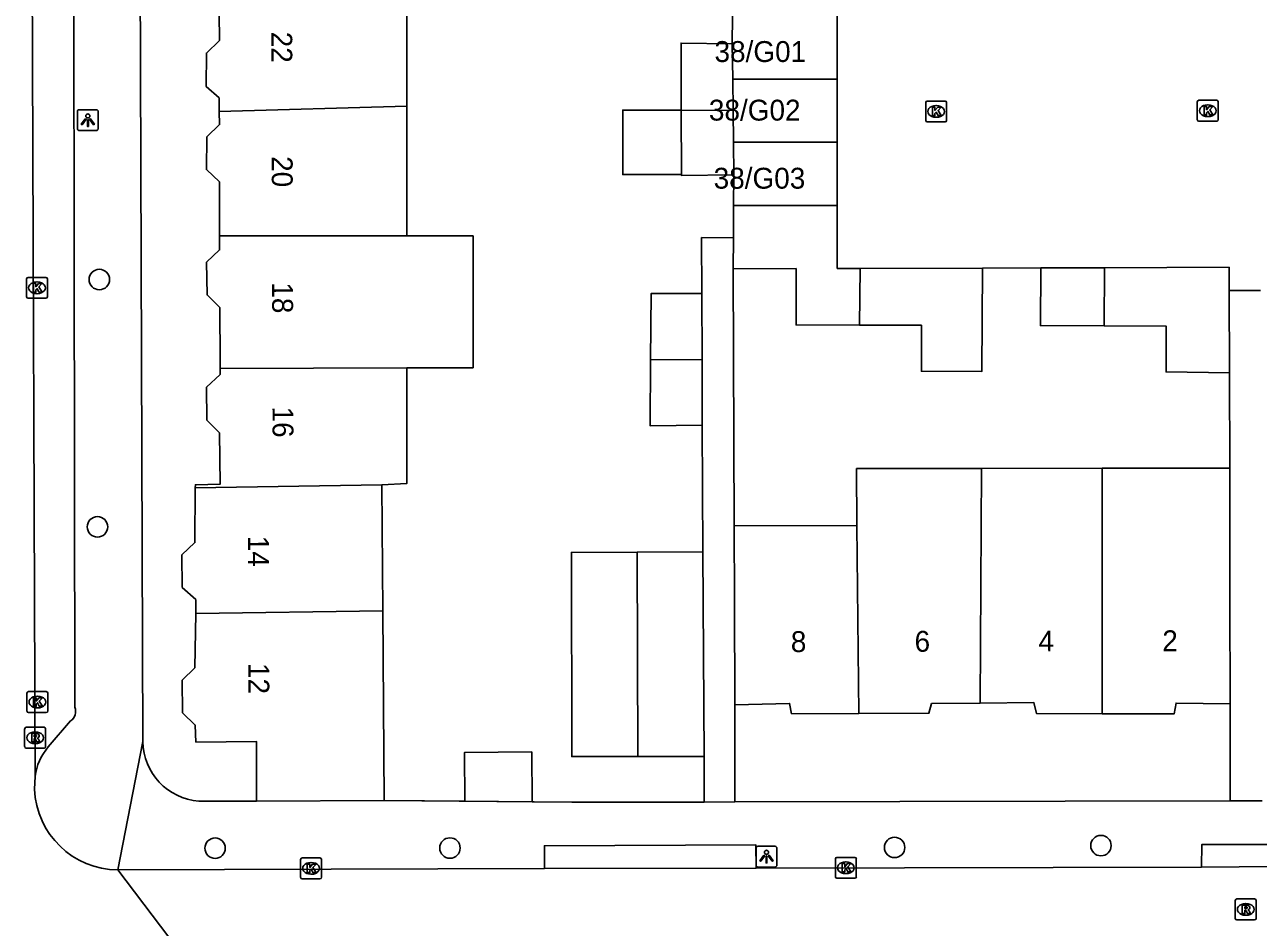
# Model space of a CAD drawing. Extents: x 160732 to 162105, y 387428 to 388479.
# Drawn here: x 161066.2 to 161125.2, y 388054.8 to 388098 of the extents above; entities that cross this region are included whole.
import ezdxf

# ---------------------------------------------------------------- set-up
doc = ezdxf.new("R2010")
doc.units = 0
for name, color, linetype in [('IMGEO_Boom', 7, 'Continuous'), ('IMGEO_Erf', 7, 'Continuous'), ('IMGEO_Kolk', 7, 'Continuous'), ('IMGEO_Lichtpunt', 7, 'Continuous'), ('IMGEO_Muur', 7, 'Continuous'), ('IMGEO_Pand', 7, 'Continuous'), ('IMGEO_Pand_nummerreeks', 7, 'Continuous'), ('IMGEO_Rijbaan_lokaal_open', 7, 'Continuous'), ('IMGEO_Rioolput', 7, 'Continuous'), ('IMGEO_Voetpad_open', 7, 'Continuous')]:
    doc.layers.add(name, color=color, linetype=linetype)

msp = doc.modelspace()

# ---------------------------------------------------------------- linework, layer by layer
at = {"layer": 'IMGEO_Boom'}
for centre in [(161069.729, 388085.825), (161069.639, 388073.982), (161075.27, 388058.596), (161086.512, 388058.605), (161107.794, 388058.632), (161117.671, 388058.72)]:
    msp.add_circle(centre, 0.489, dxfattribs=at)
at = {"layer": 'IMGEO_Erf'}
msp.add_lwpolyline([(161114.79, 388086.385), (161112.001, 388086.377)], dxfattribs=at)
at = {"layer": 'IMGEO_Kolk'}
for p, q in [((161109.283, 388093.446), (161109.283, 388094.298)), ((161109.358, 388094.372), (161110.21, 388094.372)), ((161110.284, 388094.298), (161110.284, 388093.446)), ((161122.283, 388093.482), (161122.283, 388094.334)), ((161122.358, 388094.408), (161123.21, 388094.408)), ((161123.284, 388094.334), (161123.284, 388093.482)), ((161109.771, 388094.152), (161109.796, 388094.152)), ((161122.771, 388094.188), (161122.796, 388094.188)), ((161110.21, 388093.372), (161109.358, 388093.372)), ((161109.794, 388093.592), (161109.769, 388093.592)), ((161123.21, 388093.408), (161122.358, 388093.408)), ((161122.794, 388093.628), (161122.769, 388093.628)), ((161066.245, 388085.002), (161066.245, 388085.854)), ((161066.32, 388085.928), (161067.172, 388085.928)), ((161066.733, 388085.708), (161066.758, 388085.708)), ((161067.246, 388085.854), (161067.246, 388085.002)), ((161067.172, 388084.928), (161066.32, 388084.928)), ((161066.756, 388085.148), (161066.731, 388085.148)), ((161066.263, 388065.167), (161066.263, 388066.019)), ((161066.338, 388066.093), (161067.19, 388066.093)), ((161067.264, 388066.019), (161067.264, 388065.167)), ((161066.774, 388065.313), (161066.749, 388065.313)), ((161066.751, 388065.873), (161066.776, 388065.873)), ((161067.19, 388065.093), (161066.338, 388065.093)), ((161079.362, 388057.205), (161079.362, 388058.057)), ((161079.437, 388058.131), (161080.289, 388058.131)), ((161079.85, 388057.911), (161079.875, 388057.911)), ((161080.363, 388058.057), (161080.363, 388057.205)), ((161104.961, 388057.232), (161104.961, 388058.084)), ((161105.036, 388058.158), (161105.888, 388058.158)), ((161105.449, 388057.938), (161105.474, 388057.938)), ((161105.962, 388058.084), (161105.962, 388057.232)), ((161080.289, 388057.131), (161079.437, 388057.131)), ((161079.873, 388057.351), (161079.848, 388057.351)), ((161105.888, 388057.158), (161105.036, 388057.158)), ((161105.472, 388057.378), (161105.447, 388057.378))]:
    msp.add_line(p, q, dxfattribs=at)
for points in [[(161109.283, 388093.446), (161109.283, 388094.298)], [(161109.358, 388094.372), (161110.21, 388094.372)], [(161110.284, 388094.298), (161110.284, 388093.446)], [(161122.283, 388093.482), (161122.283, 388094.334)], [(161122.358, 388094.408), (161123.21, 388094.408)], [(161123.284, 388094.334), (161123.284, 388093.482)], [(161109.604, 388094.072), (161109.727, 388094.072), (161109.727, 388093.921), (161109.857, 388094.072), (161110.021, 388094.072), (161109.875, 388093.921), (161110.028, 388093.672), (161109.876, 388093.672), (161109.791, 388093.836), (161109.727, 388093.769), (161109.727, 388093.672), (161109.604, 388093.672), (161109.604, 388094.072)], [(161122.604, 388094.108), (161122.727, 388094.108), (161122.727, 388093.957), (161122.857, 388094.108), (161123.021, 388094.108), (161122.875, 388093.957), (161123.028, 388093.708), (161122.876, 388093.708), (161122.791, 388093.872), (161122.727, 388093.805), (161122.727, 388093.708), (161122.604, 388093.708), (161122.604, 388094.108)], [(161110.21, 388093.372), (161109.358, 388093.372)], [(161123.21, 388093.408), (161122.358, 388093.408)], [(161066.245, 388085.002), (161066.245, 388085.854)], [(161066.32, 388085.928), (161067.172, 388085.928)], [(161066.566, 388085.628), (161066.689, 388085.628), (161066.689, 388085.477), (161066.819, 388085.628), (161066.983, 388085.628), (161066.837, 388085.477), (161066.99, 388085.228), (161066.838, 388085.228), (161066.753, 388085.392), (161066.689, 388085.325), (161066.689, 388085.228), (161066.566, 388085.228), (161066.566, 388085.628)], [(161067.246, 388085.854), (161067.246, 388085.002)], [(161067.172, 388084.928), (161066.32, 388084.928)], [(161066.263, 388065.167), (161066.263, 388066.019)], [(161066.338, 388066.093), (161067.19, 388066.093)], [(161067.264, 388066.019), (161067.264, 388065.167)], [(161066.584, 388065.793), (161066.707, 388065.793), (161066.707, 388065.642), (161066.837, 388065.793), (161067.001, 388065.793), (161066.855, 388065.642), (161067.008, 388065.393), (161066.856, 388065.393), (161066.771, 388065.557), (161066.707, 388065.49), (161066.707, 388065.393), (161066.584, 388065.393), (161066.584, 388065.793)], [(161067.19, 388065.093), (161066.338, 388065.093)], [(161079.362, 388057.205), (161079.362, 388058.057)], [(161079.437, 388058.131), (161080.289, 388058.131)], [(161079.683, 388057.831), (161079.806, 388057.831), (161079.806, 388057.68), (161079.936, 388057.831), (161080.1, 388057.831), (161079.954, 388057.68), (161080.107, 388057.431), (161079.955, 388057.431), (161079.87, 388057.595), (161079.806, 388057.528), (161079.806, 388057.431), (161079.683, 388057.431), (161079.683, 388057.831)], [(161080.363, 388058.057), (161080.363, 388057.205)], [(161104.961, 388057.232), (161104.961, 388058.084)], [(161105.036, 388058.158), (161105.888, 388058.158)], [(161105.282, 388057.858), (161105.405, 388057.858), (161105.405, 388057.707), (161105.535, 388057.858), (161105.699, 388057.858), (161105.553, 388057.707), (161105.706, 388057.458), (161105.554, 388057.458), (161105.469, 388057.622), (161105.405, 388057.555), (161105.405, 388057.458), (161105.282, 388057.458), (161105.282, 388057.858)], [(161105.962, 388058.084), (161105.962, 388057.232)], [(161080.289, 388057.131), (161079.437, 388057.131)], [(161105.888, 388057.158), (161105.036, 388057.158)]]:
    msp.add_lwpolyline(points, dxfattribs=at)
for centre, start, end in [((161109.36, 388094.296), 91.55205, 178.44795), ((161109.36, 388094.296), 91.55205, 178.44795), ((161110.208, 388094.296), 1.55205, 88.44795), ((161110.208, 388094.296), 1.55205, 88.44795), ((161122.36, 388094.332), 91.55205, 178.44795), ((161122.36, 388094.332), 91.55205, 178.44795), ((161123.208, 388094.332), 1.55205, 88.44795), ((161123.208, 388094.332), 1.55205, 88.44795), ((161109.36, 388093.448), 181.55205, 268.44795), ((161109.36, 388093.448), 181.55205, 268.44795), ((161110.208, 388093.448), 271.55205, 358.44795), ((161110.208, 388093.448), 271.55205, 358.44795), ((161122.36, 388093.484), 181.55205, 268.44795), ((161122.36, 388093.484), 181.55205, 268.44795), ((161123.208, 388093.484), 271.55205, 358.44795), ((161123.208, 388093.484), 271.55205, 358.44795), ((161066.322, 388085.852), 91.55205, 178.44795), ((161066.322, 388085.852), 91.55205, 178.44795), ((161067.17, 388085.852), 1.55205, 88.44795), ((161067.17, 388085.852), 1.55205, 88.44795), ((161066.322, 388085.004), 181.55205, 268.44795), ((161066.322, 388085.004), 181.55205, 268.44795), ((161067.17, 388085.004), 271.55205, 358.44795), ((161067.17, 388085.004), 271.55205, 358.44795), ((161066.34, 388066.017), 91.55205, 178.44795), ((161066.34, 388066.017), 91.55205, 178.44795), ((161067.188, 388066.017), 1.55205, 88.44795), ((161067.188, 388066.017), 1.55205, 88.44795), ((161066.34, 388065.169), 181.55205, 268.44795), ((161066.34, 388065.169), 181.55205, 268.44795), ((161067.188, 388065.169), 271.55205, 358.44795), ((161067.188, 388065.169), 271.55205, 358.44795), ((161079.439, 388058.055), 91.55205, 178.44795), ((161079.439, 388058.055), 91.55205, 178.44795), ((161080.287, 388058.055), 1.55205, 88.44795), ((161080.287, 388058.055), 1.55205, 88.44795), ((161105.038, 388058.082), 91.55205, 178.44795), ((161105.038, 388058.082), 91.55205, 178.44795), ((161105.886, 388058.082), 1.55205, 88.44795), ((161105.886, 388058.082), 1.55205, 88.44795), ((161079.439, 388057.207), 181.55205, 268.44795), ((161079.439, 388057.207), 181.55205, 268.44795), ((161080.287, 388057.207), 271.55205, 358.44795), ((161080.287, 388057.207), 271.55205, 358.44795), ((161105.038, 388057.234), 181.55205, 268.44795), ((161105.038, 388057.234), 181.55205, 268.44795), ((161105.886, 388057.234), 271.55205, 358.44795), ((161105.886, 388057.234), 271.55205, 358.44795)]:
    msp.add_arc(centre, 0.0765, start, end, dxfattribs=at)
for centre, major_axis, ratio, start_param, end_param in [((161109.77, 388093.872), (-0.387, 0.002), 0.722429, 4.712389, 7.853982), ((161109.795, 388093.872), (-0.39, 0.002), 0.717154, 1.570796, 4.712389), ((161122.77, 388093.908), (-0.387, 0.002), 0.722429, 4.712389, 7.853982), ((161122.795, 388093.908), (-0.39, 0.002), 0.717154, 1.570796, 4.712389), ((161066.732, 388085.428), (-0.387, 0.002), 0.722429, 4.712389, 7.853982), ((161066.757, 388085.428), (-0.39, 0.002), 0.717154, 1.570796, 4.712389), ((161066.75, 388065.593), (-0.387, 0.002), 0.722429, 4.712389, 7.853982), ((161066.775, 388065.593), (-0.39, 0.002), 0.717154, 1.570796, 4.712389), ((161079.849, 388057.631), (-0.387, 0.002), 0.722429, 4.712389, 7.853982), ((161079.874, 388057.631), (-0.39, 0.002), 0.717154, 1.570796, 4.712389), ((161105.448, 388057.658), (-0.387, 0.002), 0.722429, 4.712389, 7.853982), ((161105.473, 388057.658), (-0.39, 0.002), 0.717154, 1.570796, 4.712389)]:
    msp.add_ellipse(centre, major_axis=major_axis, ratio=ratio, start_param=start_param, end_param=end_param, dxfattribs=at)
at = {"layer": 'IMGEO_Lichtpunt'}
for p, q in [((161068.68, 388093.861), (161068.68, 388093.054)), ((161068.68, 388093.861), (161068.68, 388093.054)), ((161069.582, 388093.956), (161068.774, 388093.956)), ((161069.582, 388093.956), (161068.774, 388093.956)), ((161069.676, 388093.054), (161069.676, 388093.861)), ((161069.676, 388093.054), (161069.676, 388093.861)), ((161068.774, 388092.96), (161069.582, 388092.96)), ((161068.774, 388092.96), (161069.582, 388092.96)), ((161101.163, 388058.597), (161101.163, 388057.79)), ((161101.163, 388058.597), (161101.163, 388057.79)), ((161102.065, 388058.692), (161101.257, 388058.692)), ((161102.065, 388058.692), (161101.257, 388058.692)), ((161102.159, 388057.79), (161102.159, 388058.597)), ((161102.159, 388057.79), (161102.159, 388058.597)), ((161101.257, 388057.696), (161102.065, 388057.696)), ((161101.257, 388057.696), (161102.065, 388057.696))]:
    msp.add_line(p, q, dxfattribs=at)
for points in [[(161069.054, 388093.525), (161069.093, 388093.497), (161068.905, 388093.235), (161068.867, 388093.262), (161069.054, 388093.525)], [(161069.156, 388093.477), (161069.203, 388093.477), (161069.203, 388093.155), (161069.156, 388093.155), (161069.156, 388093.477)], [(161069.266, 388093.497), (161069.304, 388093.524), (161069.491, 388093.262), (161069.452, 388093.234), (161069.266, 388093.497)], [(161101.537, 388058.261), (161101.576, 388058.233), (161101.388, 388057.971), (161101.35, 388057.998), (161101.537, 388058.261)], [(161101.749, 388058.233), (161101.787, 388058.26), (161101.974, 388057.998), (161101.935, 388057.97), (161101.749, 388058.233)], [(161101.639, 388058.213), (161101.686, 388058.213), (161101.686, 388057.891), (161101.639, 388057.891), (161101.639, 388058.213)]]:
    msp.add_lwpolyline(points, dxfattribs=at)
for centre in [(161069.179, 388093.659), (161101.662, 388058.395)]:
    msp.add_circle(centre, 0.0994, dxfattribs=at)
for centre, start, end in [((161068.774, 388093.861), 90, 180), ((161068.774, 388093.861), 90, 180), ((161069.582, 388093.861), 0, 90), ((161069.582, 388093.861), 0, 90), ((161068.774, 388093.054), 180, 270), ((161068.774, 388093.054), 180, 270), ((161069.582, 388093.054), 270, 0), ((161069.582, 388093.054), 270, 360), ((161101.257, 388058.597), 90, 180), ((161101.257, 388058.597), 90, 180), ((161102.065, 388058.597), 0, 90), ((161102.065, 388058.597), 0, 90), ((161101.257, 388057.79), 180, 270), ((161101.257, 388057.79), 180, 270), ((161102.065, 388057.79), 270, 0), ((161102.065, 388057.79), 270, 360)]:
    msp.add_arc(centre, 0.0946, start, end, dxfattribs=at)
at = {"layer": 'IMGEO_Muur'}
msp.add_lwpolyline([(161083.366, 388060.882), (161092.349, 388060.795)], dxfattribs=at)
at = {"layer": 'IMGEO_Pand'}
for points in [[(161075.472, 388093.867), (161075.459, 388094.523), (161074.85, 388095.063), (161074.852, 388096.67), (161075.479, 388097.267), (161075.447, 388099.851)], [(161084.448, 388100.089), (161084.448, 388099.909), (161084.448, 388094.12)], [(161100.024, 388097.115), (161100.033, 388098.434)], [(161105.045, 388098.434), (161105.045, 388095.415)], [(161097.585, 388093.938), (161097.571, 388097.145), (161100.024, 388097.115)], [(161100.024, 388097.115), (161100.044, 388095.415)], [(161100.044, 388095.415), (161100.062, 388093.924)], [(161105.045, 388095.415), (161100.044, 388095.415)], [(161105.045, 388095.415), (161105.045, 388092.396)], [(161075.485, 388087.912), (161075.481, 388090.496), (161074.855, 388091.089), (161074.869, 388092.653), (161075.484, 388093.246), (161075.472, 388093.867)], [(161084.448, 388094.12), (161075.472, 388093.867)], [(161084.448, 388094.12), (161084.448, 388093.94), (161084.448, 388087.911)], [(161097.585, 388093.938), (161094.782, 388093.938), (161094.782, 388090.852), (161097.599, 388090.852)], [(161100.062, 388093.924), (161097.585, 388093.938)], [(161097.599, 388090.852), (161097.585, 388093.938)], [(161100.08, 388092.396), (161100.062, 388093.924)], [(161100.08, 388092.396), (161105.045, 388092.396)], [(161100.098, 388090.835), (161100.08, 388092.396)], [(161105.045, 388092.396), (161105.045, 388089.377)], [(161100.098, 388090.835), (161097.599, 388090.806), (161097.599, 388090.852)], [(161100.087, 388089.377), (161100.098, 388090.835)], [(161100.076, 388087.825), (161100.087, 388089.377)], [(161105.045, 388089.377), (161100.087, 388089.377)], [(161106.146, 388086.361), (161105.045, 388086.358), (161105.045, 388089.377)], [(161075.51, 388081.568), (161075.508, 388081.917), (161075.496, 388084.493), (161074.885, 388085.086), (161074.866, 388086.655), (161075.486, 388087.245), (161075.485, 388087.912)], [(161075.485, 388087.912), (161084.448, 388087.911)], [(161084.448, 388087.911), (161087.619, 388087.911), (161087.616, 388081.599), (161084.448, 388081.599)], [(161100.065, 388086.345), (161100.076, 388087.825)], [(161106.11, 388083.642), (161103.075, 388083.651), (161103.075, 388086.353), (161100.065, 388086.345)], [(161112.001, 388086.377), (161111.974, 388081.425), (161109.075, 388081.433), (161109.075, 388083.633), (161106.11, 388083.642)], [(161106.11, 388083.642), (161106.146, 388086.361)], [(161106.146, 388086.361), (161112.001, 388086.377)], [(161114.79, 388086.385), (161114.775, 388083.617), (161117.821, 388083.608)], [(161117.846, 388086.393), (161114.79, 388086.385)], [(161117.821, 388083.608), (161117.846, 388086.393)], [(161123.807, 388085.295), (161123.804, 388086.41), (161117.846, 388086.393)], [(161096.115, 388081.986), (161096.139, 388085.151), (161098.564, 388085.149)], [(161098.564, 388085.149), (161098.577, 388081.999)], [(161123.807, 388085.295), (161123.818, 388081.36)], [(161123.818, 388081.36), (161120.785, 388081.399), (161120.785, 388083.599), (161117.821, 388083.608)], [(161098.59, 388078.85), (161096.091, 388078.821), (161096.115, 388081.986)], [(161096.115, 388081.986), (161098.577, 388081.999)], [(161098.577, 388081.999), (161098.59, 388078.85)], [(161074.323, 388075.859), (161074.324, 388076), (161075.508, 388076.023), (161075.475, 388078.484), (161074.882, 388079.087), (161074.856, 388080.671), (161075.511, 388081.278), (161075.51, 388081.568)], [(161084.448, 388081.599), (161075.51, 388081.568)], [(161084.448, 388081.599), (161084.448, 388076.065), (161083.248, 388075.999)], [(161105.979, 388074.042), (161105.975, 388076.776), (161111.95, 388076.784)], [(161111.95, 388076.784), (161111.89, 388065.543)], [(161111.95, 388076.784), (161117.73, 388076.791)], [(161117.73, 388076.791), (161123.835, 388076.799)], [(161117.731, 388065.035), (161117.73, 388076.791)], [(161123.835, 388076.799), (161123.838, 388074.065), (161123.845, 388070.515), (161123.854, 388065.515)], [(161074.323, 388075.859), (161083.248, 388075.999)], [(161083.248, 388075.999), (161083.295, 388069.964)], [(161074.341, 388069.837), (161074.351, 388070.501), (161073.698, 388071.083), (161073.678, 388072.639), (161074.301, 388073.23), (161074.323, 388075.859)], [(161100.111, 388074.035), (161105.979, 388074.042)], [(161100.139, 388065.46), (161100.123, 388070.46), (161100.111, 388074.035)], [(161106.077, 388065.047), (161105.979, 388074.042)], [(161095.51, 388062.981), (161092.344, 388062.983), (161092.322, 388072.756), (161095.471, 388072.774)], [(161095.471, 388072.774), (161098.621, 388072.792)], [(161095.471, 388072.774), (161095.51, 388062.981)], [(161098.621, 388072.792), (161098.678, 388062.979)], [(161077.249, 388060.842), (161077.259, 388063.698), (161074.349, 388063.675), (161074.323, 388064.495), (161073.715, 388065.084), (161073.7, 388066.644), (161074.301, 388067.239), (161074.341, 388069.837)], [(161083.295, 388069.964), (161074.341, 388069.837)], [(161083.295, 388069.964), (161083.366, 388060.882)], [(161106.077, 388065.047), (161102.861, 388065.034), (161102.766, 388065.531), (161100.139, 388065.46)], [(161111.89, 388065.543), (161109.561, 388065.521), (161109.44, 388065.061), (161106.077, 388065.047)], [(161117.731, 388065.035), (161114.593, 388065.04), (161114.459, 388065.567), (161111.89, 388065.543)], [(161123.854, 388065.515), (161121.27, 388065.546), (161121.177, 388065.03), (161117.731, 388065.035)], [(161090.444, 388060.813), (161090.426, 388063.204), (161087.208, 388063.179), (161087.227, 388060.845)], [(161098.678, 388062.979), (161095.51, 388062.981)], [(161083.366, 388060.882), (161077.249, 388060.842)], [(161087.227, 388060.845), (161090.444, 388060.813)]]:
    msp.add_lwpolyline(points, dxfattribs=at)
at = {"layer": 'IMGEO_Rijbaan_lokaal_open'}
for points in [[(161066.653, 388062.032), (161066.52, 388100.574)], [(161066.653, 388062.032), (161066.63, 388061.416)], [(161101.16, 388057.648), (161091.039, 388057.619)], [(161101.16, 388057.648), (161122.48, 388057.685)], [(161129.683, 388057.754), (161122.48, 388057.685)], [(161070.621, 388057.563), (161091.039, 388057.619)], [(161075.936, 388050.523), (161070.621, 388057.563)]]:
    msp.add_lwpolyline(points, dxfattribs=at)
msp.add_arc((161070.634, 388061.57), 4.007, 182.19858, 269.81723, dxfattribs=at)
at = {"layer": 'IMGEO_Rioolput'}
for p, q in [((161066.155, 388063.458), (161066.155, 388064.31)), ((161066.23, 388064.384), (161067.082, 388064.384)), ((161066.643, 388064.164), (161066.668, 388064.164)), ((161067.156, 388064.31), (161067.156, 388063.458)), ((161066.666, 388063.604), (161066.641, 388063.604)), ((161067.082, 388063.384), (161066.23, 388063.384)), ((161124.099, 388055.238), (161124.099, 388056.09)), ((161124.174, 388056.164), (161125.026, 388056.164)), ((161124.587, 388055.944), (161124.612, 388055.944)), ((161125.1, 388056.09), (161125.1, 388055.238)), ((161124.61, 388055.384), (161124.585, 388055.384)), ((161125.026, 388055.164), (161124.174, 388055.164))]:
    msp.add_line(p, q, dxfattribs=at)
for points in [[(161066.155, 388063.458), (161066.155, 388064.31)], [(161066.23, 388064.384), (161067.082, 388064.384)], [(161067.156, 388064.31), (161067.156, 388063.458)], [(161066.744, 388064.082), (161066.492, 388064.084), (161066.492, 388063.684)], [(161066.492, 388063.684), (161066.616, 388063.684), (161066.616, 388063.846), (161066.627, 388063.846)], [(161066.67, 388064.003), (161066.616, 388064.003), (161066.616, 388063.922)], [(161066.616, 388063.922), (161066.668, 388063.922)], [(161066.674, 388063.817), (161066.745, 388063.684), (161066.885, 388063.684), (161066.82, 388063.81)], [(161067.082, 388063.384), (161066.23, 388063.384)], [(161124.099, 388055.238), (161124.099, 388056.09)], [(161124.174, 388056.164), (161125.026, 388056.164)], [(161125.1, 388056.09), (161125.1, 388055.238)], [(161124.688, 388055.862), (161124.436, 388055.864), (161124.436, 388055.464)], [(161124.436, 388055.464), (161124.56, 388055.464), (161124.56, 388055.626), (161124.571, 388055.626)], [(161124.614, 388055.783), (161124.56, 388055.783), (161124.56, 388055.702)], [(161124.56, 388055.702), (161124.612, 388055.702)], [(161124.618, 388055.597), (161124.689, 388055.464), (161124.829, 388055.464), (161124.764, 388055.59)], [(161125.026, 388055.164), (161124.174, 388055.164)]]:
    msp.add_lwpolyline(points, dxfattribs=at)
for centre, radius, start, end in [((161066.232, 388064.308), 0.0765, 91.55205, 178.44795), ((161066.232, 388064.308), 0.0765, 91.55205, 178.44795), ((161067.08, 388064.308), 0.0765, 1.55205, 88.44795), ((161067.08, 388064.308), 0.0765, 1.55205, 88.44795), ((161066.626, 388063.793), 0.0533, 26.02933, 88.69889), ((161066.652, 388064.111), 0.19, 274.7715, 282.96867), ((161066.676, 388063.907), 0.0964, 77.00612, 93.18647), ((161066.69, 388063.964), 0.0378, 276.66336, 79.67722), ((161066.743, 388063.972), 0.109, 350.36119, 89.41601), ((161066.741, 388063.972), 0.112, 277.58423, 350.98172), ((161066.725, 388063.757), 0.108, 29.51342, 73.79051), ((161066.232, 388063.46), 0.0765, 181.55205, 268.44795), ((161066.232, 388063.46), 0.0765, 181.55205, 268.44795), ((161067.08, 388063.46), 0.0765, 271.55205, 358.44795), ((161067.08, 388063.46), 0.0765, 271.55205, 358.44795), ((161124.176, 388056.088), 0.0765, 91.55205, 178.44795), ((161124.176, 388056.088), 0.0765, 91.55205, 178.44795), ((161125.024, 388056.088), 0.0765, 1.55205, 88.44795), ((161125.024, 388056.088), 0.0765, 1.55205, 88.44795), ((161124.57, 388055.573), 0.0533, 26.02933, 88.69889), ((161124.596, 388055.891), 0.19, 274.7715, 282.96867), ((161124.62, 388055.687), 0.0964, 77.00612, 93.18647), ((161124.634, 388055.744), 0.0378, 276.66336, 79.67722), ((161124.687, 388055.752), 0.109, 350.36119, 89.41601), ((161124.685, 388055.752), 0.112, 277.58423, 350.98172), ((161124.669, 388055.537), 0.108, 29.51342, 73.79051), ((161124.176, 388055.24), 0.0765, 181.55205, 268.44795), ((161124.176, 388055.24), 0.0765, 181.55205, 268.44795), ((161125.024, 388055.24), 0.0765, 271.55205, 358.44795), ((161125.024, 388055.24), 0.0765, 271.55205, 358.44795)]:
    msp.add_arc(centre, radius, start, end, dxfattribs=at)
for centre, major_axis, ratio, start_param, end_param in [((161066.642, 388063.884), (-0.387, 0.002), 0.722429, 4.712389, 7.853982), ((161066.667, 388063.884), (-0.39, 0.002), 0.717154, 1.570796, 4.712389), ((161124.586, 388055.664), (-0.387, 0.002), 0.722429, 4.712389, 7.853982), ((161124.611, 388055.664), (-0.39, 0.002), 0.717154, 1.570796, 4.712389)]:
    msp.add_ellipse(centre, major_axis=major_axis, ratio=ratio, start_param=start_param, end_param=end_param, dxfattribs=at)
at = {"layer": 'IMGEO_Voetpad_open'}
for points in [[(161071.685, 388124.043), (161071.624, 388118.893), (161071.804, 388063.698)], [(161066.995, 388122.678), (161068.185, 388121.398), (161068.479, 388120.722), (161068.559, 388065.351)], [(161098.564, 388085.149), (161098.553, 388087.836), (161100.076, 388087.825)], [(161100.111, 388074.035), (161100.065, 388086.345)], [(161125.306, 388085.299), (161123.807, 388085.295)], [(161123.818, 388081.36), (161123.835, 388076.799)], [(161098.621, 388072.792), (161098.59, 388078.85)], [(161100.148, 388060.811), (161100.139, 388065.46)], [(161123.854, 388065.515), (161123.863, 388060.859)], [(161068.355, 388064.687), (161067.287, 388063.443)], [(161071.804, 388063.698), (161070.621, 388057.563)], [(161098.682, 388060.808), (161098.678, 388062.979)], [(161074.499, 388060.849), (161077.249, 388060.842)], [(161083.366, 388060.882), (161087.227, 388060.845)], [(161090.444, 388060.813), (161092.349, 388060.795), (161098.682, 388060.808)], [(161100.148, 388060.811), (161098.682, 388060.808)], [(161123.863, 388060.859), (161100.148, 388060.811)], [(161125.382, 388060.862), (161123.863, 388060.859)], [(161091.039, 388057.619), (161091.034, 388058.713), (161101.147, 388058.758), (161101.16, 388057.648)], [(161122.48, 388057.685), (161122.499, 388058.77), (161129.729, 388058.779), (161129.683, 388057.754)]]:
    msp.add_lwpolyline(points, dxfattribs=at)
for centre, radius, start, end in [((161068.005, 388065.158), 0.587, 306.61277, 19.23029), ((161074.716, 388063.753), 2.912, 181.08731, 265.73041), ((161069.266, 388061.706), 2.633, 138.72265, 172.88603)]:
    msp.add_arc(centre, radius, start, end, dxfattribs=at)

# ---------------------------------------------------------------- texts
at = {"layer": 'IMGEO_Pand_nummerreeks'}
for s, rotation, p in [('22', 270.1781, (161077.96, 388097.69)), ('20', 270.1781, (161077.979, 388091.732)), ('18', 270.1781, (161077.998, 388085.69)), ('16', 270.1781, (161078.017, 388079.742)), ('14', 270.11756, (161076.848, 388073.553)), ('8', 0.13288, (161102.827, 388067.987)), ('6', 0.13288, (161108.751, 388068.001)), ('4', 0.13288, (161114.68, 388068.014)), ('2', 0.13288, (161120.607, 388068.028)), ('12', 270.11756, (161076.861, 388067.464))]:
    msp.add_text(s, height=1, rotation=rotation, dxfattribs=at).set_placement(p)
for s, p in [('38/G01', (161099.174, 388096.241)), ('38/G02', (161098.906, 388093.436)), ('38/G03', (161099.133, 388090.176))]:
    msp.add_text(s, height=1, dxfattribs=at).set_placement(p)

doc.saveas('drawing.dxf')
